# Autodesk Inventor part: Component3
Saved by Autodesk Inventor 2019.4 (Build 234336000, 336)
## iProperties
Created: 2020-06
Part Number: Component3
Material: Generic
Document SubType Name: Modeling
Designer: Administrator
Density: 1 g/cm^3
Appearance: Default
Title: Component3
Author: Administrator
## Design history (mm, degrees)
